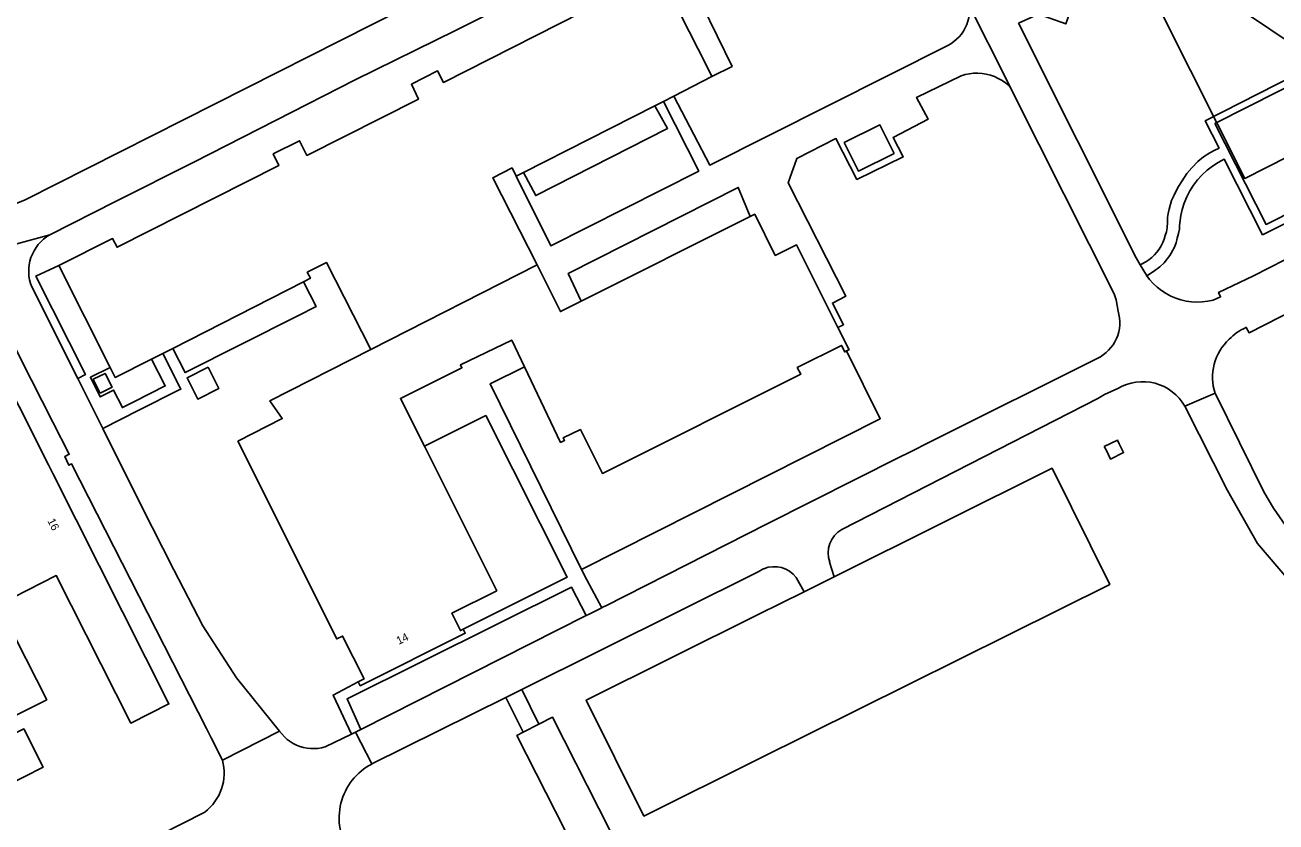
# Model space of a CAD drawing. Extents: x 158132 to 159658, y 385257 to 387209.
# Drawn here: x 158908.4 to 159064.7, y 386267.4 to 386366.9 of the extents above; entities that cross this region are included whole.
import ezdxf

# ---------------------------------------------------------------- set-up
doc = ezdxf.new("R2010")
doc.units = 0
for name, color, linetype in [('IMGEO_Groenvoorziening', 7, 'Continuous'), ('IMGEO_Lage_trafo', 7, 'Continuous'), ('IMGEO_Pand', 7, 'Continuous'), ('IMGEO_Pand_nummerreeks', 7, 'Continuous'), ('IMGEO_Pand_vergunning_verleend', 7, 'Continuous'), ('IMGEO_Parkeervlak_open', 7, 'Continuous'), ('IMGEO_Rijbaan_lokaal_gesloten', 7, 'Continuous'), ('IMGEO_Voetpad_open', 7, 'Continuous')]:
    doc.layers.add(name, color=color, linetype=linetype)

msp = doc.modelspace()

# ---------------------------------------------------------------- linework, layer by layer
at = {"layer": 'IMGEO_Groenvoorziening'}
msp.add_lwpolyline([(159011.03, 386326.25), (159015.24, 386317.78), (158977.9, 386298.96)], dxfattribs=at)
at = {"layer": 'IMGEO_Lage_trafo'}
msp.add_lwpolyline([(159043.22, 386314.33), (159043.51, 386313.81), (159043.99, 386312.73), (159045.62, 386313.56), (159045.1, 386314.58), (159045.07, 386314.64), (159044.86, 386315.12), (159043.22, 386314.33)], dxfattribs=at)
at = {"layer": 'IMGEO_Pand'}
for points in [[(158912.64, 386336.9), (158919.35, 386340.27), (158919.9, 386339.19), (158940.12, 386349.4), (158939.42, 386350.84), (158942.69, 386352.49), (158943.62, 386350.66), (158957.54, 386357.69), (158956.66, 386359.55), (158959.93, 386361.21), (158960.66, 386359.77), (158980.89, 386369.99), (158980.35, 386371.07), (158987.12, 386374.45), (158987.2, 386374.3)], [(158987.2, 386374.3), (158990.24, 386368.32), (158993.59, 386361.71), (158994.21, 386360.49)], [(158994.21, 386360.49), (158989.43, 386358.06)], [(158987.08, 386356.86), (158988.14, 386357.4)], [(158989.43, 386358.06), (158988.14, 386357.4)], [(158970.68, 386348.51), (158987.08, 386356.86)], [(159016.95, 386350.89), (159015.18, 386354.47), (159010.74, 386352.26), (159012.51, 386348.69), (159016.95, 386350.89)], [(158969.77, 386348.05), (158969.24, 386349.09), (158966.83, 386347.87), (158972.36, 386336.99)], [(158969.77, 386348.05), (158970.68, 386348.51)], [(158998.98, 386343.02), (158999.55, 386343.3), (159002.12, 386338.16), (159004.77, 386339.48), (159009.95, 386329.15)], [(158998.98, 386343.02), (158977.89, 386332.46)], [(158943.19, 386334.87), (158944.05, 386335.31), (158943.66, 386336.07), (158946.06, 386337.29), (158951.59, 386326.43)], [(158972.36, 386336.99), (158951.59, 386326.43)], [(158972.36, 386336.99), (158975.29, 386331.16), (158977.89, 386332.46)], [(158912.64, 386336.9), (158919.03, 386324.19)], [(158926.85, 386326.56), (158943.19, 386334.87)], [(158970.81, 386324.25), (158969.21, 386327.6), (158962.79, 386324.5), (158962.97, 386324.14), (158955.3, 386320.31), (158958.29, 386314.35)], [(159009.95, 386329.15), (159011.33, 386326.39), (159011.03, 386326.25)], [(158904.01, 386326.5), (158911.32, 386312.01), (158911.86, 386310.93), (158926.37, 386282.18), (158921.6, 386279.77), (158912.3, 386298.2), (158906.93, 386295.47)], [(158925.6, 386325.92), (158926.85, 386326.56)], [(158951.59, 386326.43), (158938.99, 386320.02), (158940.54, 386317.79), (158934.99, 386314.97), (158947.34, 386290.28), (158948.08, 386290.65), (158950.76, 386285.29), (158950.02, 386284.92)], [(158970.81, 386324.25), (158975.3, 386314.83), (158975.81, 386315.07), (158975.64, 386315.41), (158977.78, 386316.43), (158980.53, 386310.94), (159005.29, 386323.33), (159004.87, 386324.16), (159010.4, 386326.93), (159010.8, 386326.13), (159011.03, 386326.25)], [(158924.21, 386325.22), (158919.68, 386322.91), (158919.03, 386324.19)], [(158924.21, 386325.22), (158925.6, 386325.92)], [(158917.8, 386320.96), (158919.27, 386321.7), (158918.4, 386323.43), (158916.93, 386322.7), (158917.8, 386320.96)], [(158963.13, 386291.5), (158962.79, 386291.33), (158961.71, 386293.5), (158967.32, 386296.31), (158958.29, 386314.35)], [(158904.2, 386294.12), (158899.8, 386291.9), (158900.63, 386290.25), (158905.94, 386292.93), (158911.11, 386282.69), (158905.8, 386280.01), (158906.68, 386278.26), (158908.25, 386279.05), (158910.67, 386274.26), (158895.87, 386266.79), (158893.68, 386271.15), (158892.7, 386270.65), (158894.89, 386266.3)], [(158963.13, 386291.5), (158963.39, 386291), (158950.27, 386284.43), (158950.02, 386284.92)], [(158970.61, 386278.64), (158969.84, 386278.24), (158977.09, 386263.98), (158981.55, 386266.24), (158974.3, 386280.51), (158972.59, 386279.64)], [(158970.61, 386278.64), (158972.59, 386279.64)]]:
    msp.add_lwpolyline(points, dxfattribs=at)
at = {"layer": 'IMGEO_Pand_vergunning_verleend'}
msp.add_lwpolyline([(159050.57, 386368.04), (159057.32, 386371.44), (159056.43, 386373.19), (159088.1, 386389.15), (159085.8, 386393.7), (159116.59, 386409.22), (159123.52, 386395.49), (159125.08, 386396.27), (159128.07, 386390.33), (159124.61, 386388.59), (159130.93, 386376.07), (159110.74, 386365.89), (159098.15, 386390.88), (159089.73, 386386.63), (159092.11, 386381.91), (159085.18, 386378.43), (159091.59, 386365.71), (159079.32, 386359.4), (159081.2, 386355.82), (159075.09, 386353.07), (159074.31, 386354.62), (159060.77, 386347.79), (159050.57, 386368.04)], dxfattribs=at)
at = {"layer": 'IMGEO_Parkeervlak_open'}
msp.add_lwpolyline([(159009.48, 386298.05), (159036.7, 386311.59), (159043.9, 386297.1), (159000, 386275.27), (158985.7, 386268.16), (158978.5, 386282.65), (159000, 386293.34), (159005.72, 386296.18)], dxfattribs=at)
at = {"layer": 'IMGEO_Rijbaan_lokaal_gesloten'}
for points in [[(159004.59, 386393.75), (158971.38, 386376.95), (158932.17, 386357.09), (158908.42, 386345.13), (158904.98, 386343.72), (158901.43, 386342.6), (158897.8, 386341.78), (158894.12, 386341.27), (158874.52, 386341.06)], [(158911.49, 386340.74), (158919.69, 386344.89), (158929.51, 386349.82), (158939.71, 386355.02), (158949.66, 386360.11), (158962.18, 386366.26), (158976.95, 386373.68), (158986.06, 386378.31)], [(159031.5, 386359.15), (159025.97, 386370.17)], [(159047.71, 386337.01), (159047.2, 386337.87), (159032.5, 386367.15)], [(158980.44, 386294.18), (158980.55, 386294.24), (158980.85, 386294.39), (159001.11, 386304.67), (159017.64, 386312.98), (159018.75, 386313.54), (159021.71, 386315.03), (159042.34, 386325.31), (159042.73, 386325.52), (159043.09, 386325.76), (159043.44, 386326.03), (159043.76, 386326.34), (159044.05, 386326.66), (159044.31, 386327.02), (159044.54, 386327.39), (159044.73, 386327.78), (159044.89, 386328.19), (159045.02, 386328.61), (159045.1, 386329.04), (159045.15, 386329.48), (159045.15, 386329.92), (159045.12, 386330.36), (159045.05, 386330.79), (159044.95, 386331.22), (159044.7, 386332.62), (159044.44, 386333.38), (159031.93, 386358.27), (159031.5, 386359.15)], [(159079.47, 386344.62), (159061.86, 386335.62), (159057.49, 386333.55), (159057.75, 386333.01), (159056.8, 386332.6), (159056.14, 386332.46), (159055.46, 386332.37), (159054.79, 386332.35), (159054.11, 386332.38), (159053.45, 386332.47), (159052.79, 386332.63), (159052.14, 386332.83), (159051.52, 386333.1), (159050.93, 386333.41), (159050.36, 386333.78), (159049.83, 386334.2), (159049.33, 386334.66), (159048.88, 386335.16), (159048.54, 386335.62)], [(158911.49, 386340.74), (158897.88, 386337.03)], [(158914.98, 386322.8), (158909.25, 386334.23), (158909.09, 386334.67), (158908.97, 386335.12), (158908.9, 386335.59), (158908.87, 386336.05), (158908.88, 386336.52), (158908.93, 386336.99), (158909.02, 386337.45), (158909.15, 386337.9), (158909.32, 386338.34), (158909.54, 386338.76), (158909.78, 386339.16), (158910.06, 386339.53), (158910.38, 386339.88), (158910.72, 386340.2), (158911.09, 386340.49), (158911.22, 386340.57), (158911.49, 386340.74)], [(158897.88, 386337.03), (158900.47, 386336.33), (158902.56, 386335.77), (158906.58, 386327.8), (158909.22, 386322.6), (158911.89, 386317.33), (158913.92, 386313.34), (158913.36, 386313.05), (158913.89, 386311.97), (158914.23, 386312.13), (158931.06, 386279.11), (158931.65, 386277.95), (158933.07, 386275.16)], [(159048.54, 386335.62), (159048.48, 386335.7), (159047.71, 386337.01)], [(159070.85, 386333.39), (159061.3, 386328.52), (159060.94, 386329.18), (159060.89, 386329.16)], [(158918.11, 386316.57), (158914.98, 386322.8)], [(159010.43, 386303.94), (159042.4, 386320.3), (159043.26, 386320.8), (159044.91, 386321.54)], [(159053.26, 386319.34), (159057.06, 386320.95)], [(159057.06, 386320.95), (159063.13, 386308.66), (159064.37, 386306.62), (159065.84, 386304.45), (159069.55, 386299.85), (159072.07, 386297.13), (159075.2, 386294.37), (159080.13, 386290.27)], [(159083.09, 386281.45), (159081.83, 386282.69), (159080.46, 386284.34), (159075.76, 386288.34), (159072.25, 386291.43), (159069.75, 386293.86), (159066.47, 386297.37), (159062.37, 386302.2), (159058.59, 386308.8), (159053.26, 386319.34)], [(158940.2, 386278.78), (158934.82, 386285.43), (158930.6, 386291.94), (158927.01, 386298.91), (158922.92, 386306.95), (158918.11, 386316.57)], [(159009.48, 386298.05), (159008.91, 386299.86)], [(158970.44, 386283.97), (158999.99, 386298.66), (159000.7, 386299.06)], [(159004.74, 386297.96), (159005.72, 386296.18)], [(159005.72, 386296.18), (159009.48, 386298.05)], [(158978.5, 386293.2), (158978.89, 386293.39), (158980.44, 386294.18)], [(158950.33, 386278.96), (158978.5, 386293.2)], [(158970.44, 386283.97), (158968.45, 386282.98)], [(158951.73, 386274.67), (158968.45, 386282.98)], [(158933.07, 386275.16), (158940.2, 386278.78)], [(158949.18, 386278.38), (158945.89, 386276.8), (158945.45, 386276.69), (158944.99, 386276.62), (158944.54, 386276.59), (158944.08, 386276.6), (158943.63, 386276.65), (158943.18, 386276.74), (158942.74, 386276.87), (158942.31, 386277.04), (158941.9, 386277.24), (158941.51, 386277.47), (158941.14, 386277.74), (158940.8, 386278.04), (158940.2, 386278.78)], [(158949.18, 386278.38), (158949.68, 386278.64)], [(158949.68, 386278.64), (158950.33, 386278.96)], [(158951.73, 386274.67), (158949.68, 386278.64)], [(158930.86, 386268.67), (158894.07, 386250), (158864.7, 386235.1), (158863.71, 386234.82)]]:
    msp.add_lwpolyline(points, dxfattribs=at)
for centre, radius, start, end in [((159063.76, 386322.84), 6.94, 114.4185, 135.4357), ((159063.24, 386322.95), 6.5, 132.9212, 197.984), ((159048.01, 386316.38), 6.03, 29.4306, 120.9255), ((159012.05, 386301.02), 3.34, 119.032, 200.1396), ((159002, 386295.87), 3.44, 37.3554, 112.2617), ((158927.16, 386273.55), 6.12, 307.0735, 15.2059), ((158955.21, 386267.94), 7.57, 117.3529, 214.5917)]:
    msp.add_arc(centre, radius, start, end, dxfattribs=at)
at = {"layer": 'IMGEO_Voetpad_open'}
for points in [[(158987.2, 386378.88), (158989.06, 386375.25), (158989.8, 386375.63), (158992.99, 386369.41), (158996.72, 386361.77), (158994.21, 386360.49)], [(159067.3, 386364.12), (159060.59, 386368.62), (159059.98, 386368.98), (159059.33, 386369.28), (159058.67, 386369.53), (159057.99, 386369.73), (159057.29, 386369.87), (159051.53, 386371.06), (159050.99, 386371.13), (159050.47, 386371.24), (159049.95, 386371.4), (159049.45, 386371.6), (159048.97, 386371.84), (159048.51, 386372.12), (159048.08, 386372.45), (159047.68, 386372.8), (159046.75, 386373.98), (159039.66, 386370.62), (159038.4, 386367.08), (159034.99, 386368.3), (159032.5, 386367.15)], [(159025.97, 386370.17), (159026.11, 386369.68), (159026.28, 386369.11), (159026.36, 386368.74), (159026.36, 386368.29), (159026.29, 386367.85), (159026.18, 386367.41), (159026.04, 386366.99), (159025.85, 386366.58), (159025.63, 386366.18), (159025.38, 386365.81), (159025.09, 386365.47), (159024.77, 386365.15), (159024.43, 386364.86), (159024.05, 386364.6), (159023.66, 386364.38), (158993.94, 386349.44), (158989.43, 386358.06)], [(159057.02, 386354.63), (159080.92, 386366.72), (159087.34, 386354.08), (159063.42, 386342.05), (159057.02, 386354.63)], [(159009.95, 386329.15), (159010.65, 386329.51), (159009.26, 386332.21), (159010.94, 386333.1), (159003.74, 386347.25), (159004.83, 386350.29), (159009.7, 386352.76), (159012.32, 386347.66), (159018.1, 386350.48), (159016.84, 386352.9), (159021.2, 386355.18), (159019.76, 386357.9), (159025.33, 386360.61), (159025.84, 386360.75), (159026.36, 386360.85), (159026.89, 386360.91), (159027.42, 386360.92), (159027.95, 386360.88), (159028.48, 386360.8), (159028.99, 386360.67), (159029.5, 386360.5), (159029.98, 386360.28), (159030.45, 386360.02), (159030.89, 386359.73), (159031.3, 386359.39), (159031.5, 386359.15)], [(159047.71, 386337.01), (159048.39, 386337.35), (159048.78, 386337.62), (159049.14, 386337.91), (159049.47, 386338.23), (159049.78, 386338.59), (159050.05, 386338.96), (159050.3, 386339.36), (159050.51, 386339.77), (159050.68, 386340.21), (159050.82, 386340.65), (159050.98, 386341.13), (159051.07, 386341.63), (159051.11, 386342.34), (159051.12, 386342.89), (159051.19, 386343.39), (159051.3, 386343.95), (159051.62, 386345.02), (159051.93, 386345.71), (159052.41, 386346.63), (159052.93, 386347.47), (159053.53, 386348.39), (159054.14, 386349.12), (159054.91, 386349.89), (159055.62, 386350.48), (159056.38, 386350.99), (159056.95, 386351.26), (159057.55, 386351.57), (159055.82, 386354.97), (159069.13, 386361.77)], [(158988.14, 386357.4), (158992.55, 386348.69), (158974.07, 386339.37), (158969.77, 386348.05)], [(158970.68, 386348.51), (158972.19, 386345.65), (158988.66, 386354.02), (158987.08, 386356.86)], [(159077.74, 386348.16), (159062.98, 386340.74), (159058.2, 386350.17), (159057.45, 386349.79), (159056.74, 386349.33), (159056.07, 386348.82), (159055.44, 386348.25), (159054.87, 386347.62), (159054.36, 386346.95), (159053.9, 386346.24), (159053.52, 386345.49), (159053.19, 386344.71), (159052.94, 386343.9), (159052.76, 386343.17), (159052.63, 386341.89), (159052.6, 386341.43), (159052.5, 386340.92), (159052.33, 386340.33), (159052.19, 386339.73), (159051.94, 386339.11), (159051.4, 386338.17), (159050.68, 386337.23), (159050.14, 386336.76), (159049.35, 386336.17), (159048.54, 386335.62)], [(158977.89, 386332.46), (158976.26, 386335.91), (158997.49, 386346.67), (158998.98, 386343.02)], [(158914.98, 386322.8), (158915.94, 386323.29), (158909.76, 386335.59), (158912.64, 386336.9)], [(158943.19, 386334.87), (158944.76, 386331.78), (158942.46, 386330.61), (158928.39, 386323.54), (158926.85, 386326.56)], [(158919.03, 386324.19), (158916.57, 386322.95), (158917.8, 386320.51), (158919.47, 386321.35), (158920.56, 386319.18), (158922.06, 386319.93), (158925.92, 386321.87), (158924.21, 386325.22)], [(158925.6, 386325.92), (158927.87, 386321.47), (158927.57, 386321.33), (158922.61, 386318.84), (158918.11, 386316.57)], [(158931.28, 386324.22), (158932.62, 386321.57), (158929.98, 386320.24), (158928.64, 386322.89), (158931.28, 386324.22)], [(158977.9, 386298.96), (158966.51, 386322.14), (158970.81, 386324.25)], [(158958.29, 386314.35), (158965.97, 386318.17), (158976.13, 386298.01), (158963.13, 386291.5)], [(158980.44, 386294.18), (158978.58, 386297.68), (158977.9, 386298.96)], [(158950.33, 386278.96), (158948.63, 386282.81), (158976.67, 386296.74), (158978.5, 386293.2)], [(158950.02, 386284.92), (158946.89, 386283.27), (158949.18, 386278.38)], [(158972.59, 386279.64), (158970.44, 386283.97)], [(158968.45, 386282.98), (158970.61, 386278.64)]]:
    msp.add_lwpolyline(points, dxfattribs=at)

# ---------------------------------------------------------------- texts
at = {"layer": 'IMGEO_Pand_nummerreeks'}
for s, rotation, p in [('16', 296.8486, (158911.17, 386305.03)), ('14', 25.7201, (158955.08, 386289.54))]:
    msp.add_text(s, height=1, rotation=rotation, dxfattribs=at).set_placement(p)

doc.saveas('drawing.dxf')
